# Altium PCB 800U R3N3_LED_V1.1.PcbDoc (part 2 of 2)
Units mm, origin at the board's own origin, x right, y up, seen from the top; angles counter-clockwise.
Board outline 308.48 x 220.22 mm, 4 copper layers (Top Layer, GND, Mid-Layer 2, Bottom Layer); 79 components, 48 nets, 220 pads, 97 vias.
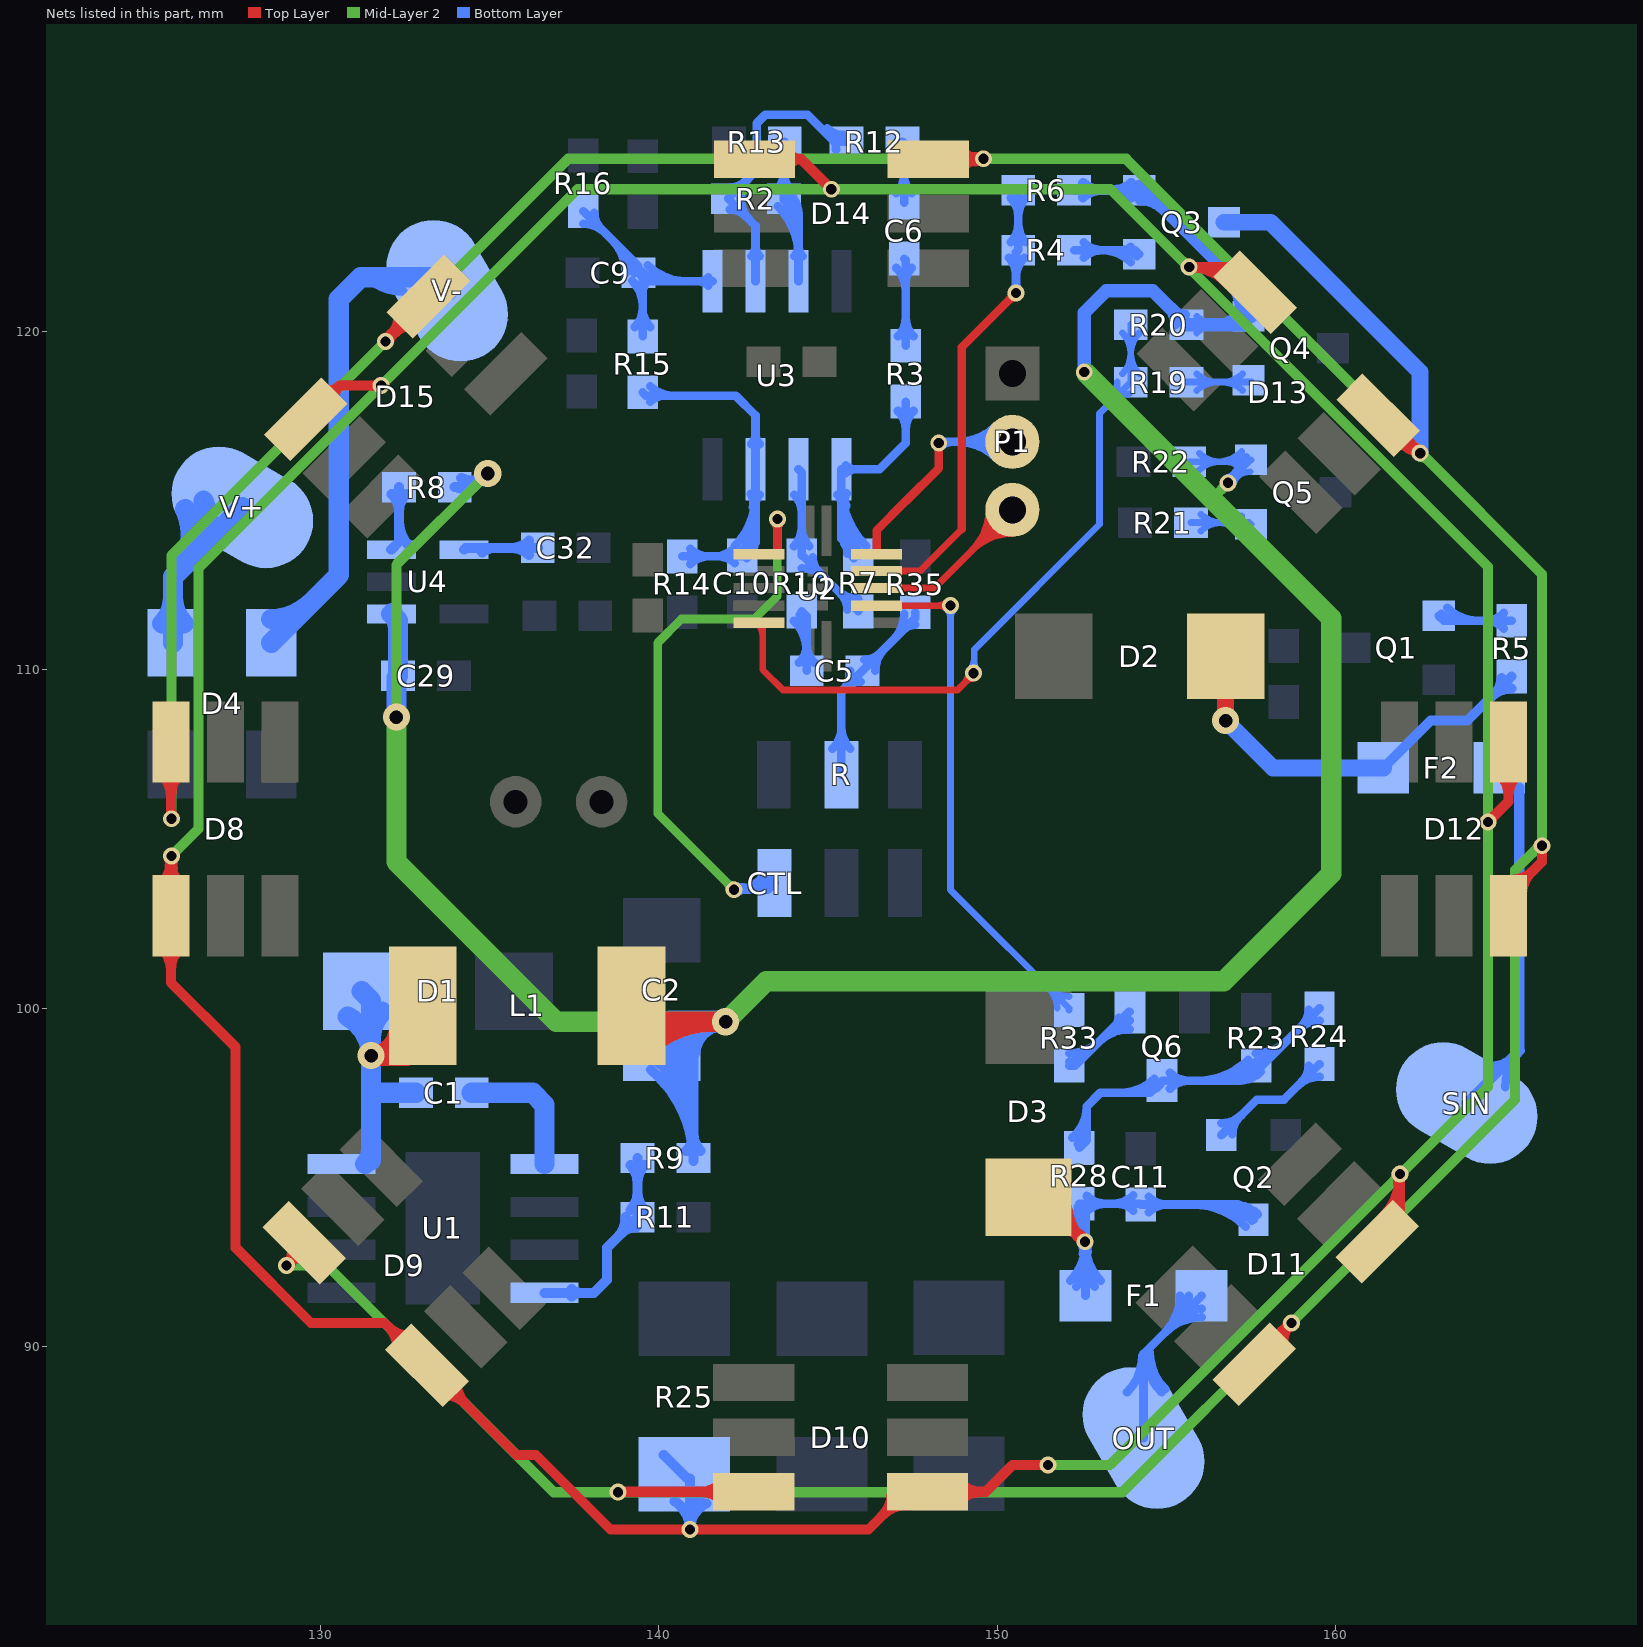
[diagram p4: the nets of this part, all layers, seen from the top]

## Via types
v1: diameter 0.5, hole 0.3, Top Layer to Bottom Layer, 88 vias
v2: diameter 0.8, hole 0.4, Top Layer to Bottom Layer, 6 vias
v3: diameter 0.6, hole 0.3, Top Layer to Bottom Layer, 3 vias

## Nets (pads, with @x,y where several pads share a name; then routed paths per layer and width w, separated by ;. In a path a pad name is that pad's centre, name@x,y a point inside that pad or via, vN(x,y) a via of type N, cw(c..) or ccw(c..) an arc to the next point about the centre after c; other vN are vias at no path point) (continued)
LED_G: R19.2 R20.2 U2.5 | length 26
  Top Layer w0.2: U2.5@142.925,111.356 cw(c142.564,110.995) 143.075,110.995 ; U2.5@142.963,111.393 143.075,111.281 143.075,110 143.675,109.4 148.825,109.4 v1@149.325,109.9 ; 149.026,109.601 ccw(c148.728,109.9) v1@149.15,109.9 ; 149.087,109.662 cw(c149.3,109.448) v1@149.3,109.75
  Bottom Layer w0.2: v1@149.194,110.006 ccw(c148.878,110.322) 149.325,110.322 ; v1@149.325,109.8 149.325,110.6 153.025,114.3 153.025,117.575 R19.2@153.95,118.5 R20.2@153.95,120.2 ; 149.325,110.202 ccw(c149.602,110.202) v1@149.406,110.006 ; 153.267,117.817 ccw(c152.584,118.5) R19.2@153.55,118.5 ; 153.388,117.938 cw(c153.9,117.426) R19.2@153.9,118.15 ; R19.2@153.703,118.747 ccw(c153.105,119.345) 153.95,119.345 ccw(c154.795,119.345) R19.2@154.197,118.747 ; R20.2@153.703,119.953 cw(c153.105,119.355) 153.95,119.355 cw(c154.795,119.355) R20.2@154.197,119.953
  other v1: 149.3,109.9
LED_R: R4.2 R6.2 U2.9 | length 18.4
  Top Layer w0.2: U2.9@146.437,112.918 147.718,112.918 148.95,114.15
  Top Layer w0.254: 148.95,114.15 148.95,119.524 v1(150.557,121.131) ; v1@150.434,121.131 cw(c150.137,121.131) 150.347,120.921 cw(c150.557,120.711) v1@150.557,121.008
  Mid-Layer 2 w0.254: v1(150.557,121.131) v1@150.557,121.182
  Bottom Layer w0.254: R4.2@150.347,122.172 cw(c149.838,121.663) 150.557,121.663 ; R4.2@150.397,122.628 ccw(c149.845,123.18) 150.625,123.18 ccw(c151.405,123.18) R4.2@150.853,122.628 ; R6.2@150.397,123.947 cw(c149.845,123.395) 150.625,123.395 cw(c151.405,123.395) R6.2@150.853,123.947 ; v1@150.47,121.218 ccw(c150.26,121.428) 150.557,121.428 ccw(c150.854,121.428) v1@150.644,121.218 ; v1(150.557,121.131) 150.557,122.332 R4.2@150.625,122.4 R6.2@150.625,124.175 ; 150.557,121.578 cw(c151.397,121.578) R4.2@150.803,122.172
LEDCTL: CTL.1 U2.1 | length 21.7
  Top Layer w0.254: U2.1@142.963,113.418 143.507,113.418 v1(143.507,114.456) ; v1@143.42,114.369 cw(c143.211,114.16) 143.507,114.16 ; 143.507,113.609 ccw(c143.751,113.609) U2.1@143.578,113.436 ; 143.507,114.157 cw(c143.805,114.157) v1@143.594,114.369
  Mid-Layer 2 w0.254: v1@142.102,103.5 ccw(c141.805,103.5) 142.015,103.71 ccw(c142.225,103.92) v1@142.225,103.623 ; v1(142.225,103.5) 139.975,105.75 139.975,110.8 140.675,111.5 142.825,111.5 143.507,112.182 v1(143.507,114.456) ; v1@143.42,114.369 cw(c143.21,114.159) 143.507,114.159 cw(c143.804,114.159) v1@143.594,114.369
  Bottom Layer w0.254: v1@142.286,103.607 ccw(c142.435,103.864) 142.512,103.577 ccw(c142.589,103.29) v1@142.332,103.438 ; v1@142.312,103.413 cw(c142.522,103.203) 142.522,103.5 cw(c142.522,103.797) v1@142.312,103.587 ; 142.757,103.5 ccw(c142.757,104.24) CTL.1@143.332,103.775 ; CTL.1@143.135,103.934 cw(c142.225,104.67) v1(142.225,103.5) 143.225,103.5 CTL.1@143.425,103.7
NetC1_1: C1.1 U1.1 | length 4
  Bottom Layer w0.6: C1.1@134.475,97.5 136.275,97.5 136.625,97.15 U1.1@136.625,95.4
NetC1_2: C1.2 D1.2 L1.1 U1.8 | length 13.4
  Top Layer w0.6: L1.1@132.147,98.6 ccw(c132.147,99.383) L1.1@132.928,99.325 ; L1.1@132.33,99.369 cw(c131.5,99.432) v2(131.5,98.6) L1.1@132.561,98.6 ; L1.1@132.498,99.537 L1.1@133.028,100.067
  Bottom Layer w0.6: D1.2@130.81,99.758 cw(c130.15,98.58) v2@131.5,98.58 ; D1.2@131.225,100.5 131.5,100.225 v2(131.5,98.6) U1.8@131.5,95.5 ; U1.8@131.325,95.4 ccw(c130.903,95.822) 131.5,95.822 ; 131.5,97.5 C1.2@132.825,97.5 ; 131.5,99.112 cw(c132.613,99.112) D1.2@131.826,99.899
NetC5_1: C5.1 R35.1 R.1 | length 10.8
  Bottom Layer w0.254: R.1@145.136,107.664 ccw(c144.5,108.3) 145.4,108.3 ccw(c146.3,108.3) R.1@145.664,107.664 ; R.1@145.4,106.9 145.4,109.35 ; 145.509,109.459 cw(c145.975,108.993) C5.1@145.975,109.652 ; C5.1@145.652,109.971 cw(c144.791,109.959) 145.4,109.35 ; C5.1@146.075,110.298 ccw(c146.075,110.957) 146.541,110.491 ; C5.1@146.398,109.975 cw(c147.298,109.975) 146.662,110.612 ; 146.935,110.885 ccw(c146.17,111.65) R35.1@147.252,111.65 ; 147.237,111.187 cw(c147.575,110.849) R35.1@147.575,111.327 ; R35.1@147.575,111.7 147.575,111.525 C5.1@146.025,109.975 145.4,109.35
NetC5_2: C5.2 R10.1 | length 4.6
  Bottom Layer w0.254: R10.1@143.997,111.447 cw(c143.083,110.533) 144.375,110.533 ; C5.2@144.147,110.203 ccw(c143.595,110.755) 144.375,110.755 ccw(c145.155,110.755) C5.2@144.603,110.203 ; R10.1@144.176,111.626 cw(c143.696,111.146) 144.375,111.146 ; R10.1@144.225,111.725 144.375,111.575 C5.2@144.375,109.975
NetC6_1: C6.1 R3.2 | length 5
  Bottom Layer w0.254: C6.1@147.022,121.872 cw(c146.35,121.2) 147.3,121.2 ; R3.2@147.072,119.853 ccw(c146.52,120.405) 147.3,120.405 ccw(c148.08,120.405) R3.2@147.528,119.853 ; C6.1@147.25,122.15 147.3,122.1 R3.2@147.3,119.575 ; 147.3,121.441 cw(c147.909,121.441) C6.1@147.478,121.872
NetC6_2: C6.2 R12.1 | length 4.3
  Bottom Layer w0.254: C6.2@147.022,124.078 ccw(c146.47,124.63) 147.25,124.63 ccw(c148.03,124.63) C6.2@147.478,124.078 ; R12.1@147.022,125.372 cw(c146.47,124.82) 147.25,124.82 cw(c148.03,124.82) R12.1@147.478,125.372 ; R12.1@147.2,125.6 147.25,125.55 C6.2@147.25,123.8
NetC9_1: C9.1 R15.2 R16.2 U3.5 | length 14.6
  Bottom Layer w0.254: R16.2@137.775,123.177 cw(c137.775,122.276) 138.412,122.913 ; R16.2@137.775,123.55 139.4,121.925 C9.1@139.4,121.725 C9.1@139.525,121.6 ; R16.2@138.098,123.5 ccw(c138.757,123.5) 138.291,123.034 ; 138.622,122.703 cw(c137.644,121.725) C9.1@139.027,121.725 ; 139.055,122.27 cw(c138.511,121.725) C9.1@139.281,121.725 ; C9.1@139.222,121.497 cw(c138.489,120.764) 139.525,120.764 ; R15.2@139.297,120.128 ccw(c138.745,120.68) 139.525,120.68 ccw(c140.305,120.68) R15.2@139.753,120.128 ; C9.1@139.499,121.774 ccw(c140.22,122.495) 140.22,121.475 ; R15.2@139.525,119.85 C9.1@139.525,121.6 ; 139.525,121.126 cw(c140.049,121.126) C9.1@139.678,121.497 ; C9.1@139.678,121.953 ccw(c140.833,123.108) 140.833,121.475 ; U3.5@141.468,121.353 ccw(c141.172,121.057) 141.172,121.475 ccw(c141.172,121.893) U3.5@141.468,121.597 ; U3.5@141.59,121.475 139.65,121.475 C9.1@139.525,121.6
NetC10_1: C10.1 R14.2 R15.1 U3.3 | length 18.8
  Bottom Layer w0.254: R15.1@139.525,118.2 139.625,118.1 142.275,118.1 142.86,117.515 U3.3@142.86,115.925 142.86,113.76 C10.1@142.475,113.375 142.45,113.35 R14.2@140.7,113.35 ; R15.1@139.753,117.922 cw(c140.184,117.491) 140.184,118.1 ; R15.1@139.753,118.378 ccw(c140.425,119.05) 140.425,118.1 ; R14.2@140.928,113.122 cw(c141.48,112.57) 141.48,113.35 cw(c141.48,114.13) R14.2@140.928,113.578 ; 141.635,113.35 ccw(c141.635,114.215) C10.1@142.247,113.603 ; 141.756,113.35 cw(c141.756,112.656) C10.1@142.247,113.147 ; C10.1@142.247,113.653 ccw(c140.766,115.134) U3.3@142.86,115.134 ; C10.1@142.426,113.474 ccw(c141.379,114.521) 142.86,114.521 ; C10.1@142.606,113.294 ccw(c141.992,113.908) 142.86,113.908 ; U3.3@142.714,115.207 cw(c142.261,114.916) 142.787,114.801 ; U3.3@142.738,115.178 cw(c142.442,114.882) 142.86,114.882 cw(c143.278,114.882) U3.3@142.982,115.178 ; U3.3@142.738,116.672 ccw(c142.442,116.968) 142.86,116.968 ccw(c143.278,116.968) U3.3@142.982,116.672 ; 142.824,114.968 cw(c143.113,114.905) U3.3@142.953,115.154
NetC11_1: C11.1 D3.2 F1.2 Q2.3 R28.2 | length 32.7
  Top Layer w0.254: D3.2@150.925,94.42 151.28,94.42 v1(152.6,93.1) ; D3.2@151.186,93.93 cw(c151.402,93.139) D3.2@151.981,93.719 ; D3.2@151.253,93.685 cw(c151.534,92.653) 152.291,93.409 ; D3.2@151.32,93.44 cw(c151.667,92.167) v1(152.6,93.1) ; D3.2@151.814,94.411 ccw(c153.043,94.395) D3.2@152.174,93.526 ; D3.2@152.068,94.407 ccw(c153.885,94.385) v1(152.6,93.1) ; v1@152.477,93.1 ccw(c152.18,93.1) 152.39,93.31 ccw(c152.6,93.52) v1@152.6,93.223 ; v1@152.481,93.068 ccw(c152.194,92.991) 152.343,93.249 ccw(c152.491,93.506) v1@152.568,93.219 ; v1@152.481,93.132 ccw(c152.194,93.209) 152.452,93.357 ccw(c152.709,93.506) v1@152.632,93.219
  Bottom Layer w0.254: F1.2@152.161,91.949 ccw(c151.077,93.033) 152.61,93.033 ccw(c154.144,93.033) F1.2@153.06,91.949 ; R28.2@152.197,93.947 cw(c151.197,92.947) v1@152.61,92.947 ; F1.2@152.341,91.769 ccw(c151.691,92.42) 152.61,92.42 ccw(c153.53,92.42) F1.2@152.88,91.769 ; R28.2@152.376,94.126 cw(c151.811,93.561) 152.61,93.561 ; 152.476,93.448 ccw(c152.86,93.55) v1@152.661,93.207 ; v1@152.493,93.039 cw(c152.155,92.843) 152.533,92.742 ; v1@152.513,93.013 cw(c152.278,92.778) 152.61,92.778 ; v1@152.513,93.187 ccw(c152.278,93.422) 152.61,93.422 ; v1@152.538,92.993 cw(c152.402,92.758) 152.665,92.828 ; F1.2@152.61,91.5 152.61,94.04 R28.2@152.425,94.225 154.225,94.225 C11.1@154.25,94.2 157.125,94.2 Q2.3@157.575,93.75 ; 152.61,92.828 cw(c152.872,92.828) v1@152.687,93.013 ; 152.61,93.372 ccw(c152.872,93.372) v1@152.687,93.187 ; R28.2@152.653,93.997 cw(c153.205,93.445) 153.205,94.225 cw(c153.205,95.005) R28.2@152.653,94.453 ; 152.674,92.795 cw(c152.985,92.878) v1@152.707,93.038 ; 153.41,94.225 ccw(c153.41,95.09) C11.1@154.022,94.478 ; 153.531,94.225 cw(c153.531,93.531) C11.1@154.022,94.022 ; C11.1@154.478,93.972 cw(c155.03,93.42) 155.03,94.2 cw(c155.03,94.98) C11.1@154.478,94.428 ; 155.769,94.2 cw(c155.769,91.969) Q2.3@157.347,93.547 ; 156.382,94.2 cw(c156.382,92.582) Q2.3@157.526,93.726 ; 156.996,94.2 cw(c156.996,93.196) Q2.3@157.706,93.906
NetC32_1: C32.1 U4.4 | length 3.7
  Bottom Layer w0.3: U4.4@134.25,113.55 134.3,113.6 C32.1@136.425,113.6 ; U4.4@134.788,113.462 cw(c135.122,113.128) 135.122,113.6 ; C32.1@136.163,113.388 ccw(c135.651,112.876) 135.651,113.6 ccw(c135.651,114.324) C32.1@136.163,113.812
NetD2_2: D2.2 F2.1 R5.1 | length 13.2
  Top Layer w0.3: D2.2@156.75,110.395 D2.2@156.755,110.4
  Top Layer w0.5: v2(156.75,108.5) D2.2@156.75,110.395
  Bottom Layer w0.3: F2.1@161.411,107.1 162.811,108.5 163.9,108.5 R5.1@165.2,109.8 ; 164.603,109.203 cw(c165.2,108.605) R5.1@165.2,109.45 ; 164.723,109.323 ccw(c164.296,109.75) R5.1@164.9,109.75
  Bottom Layer w0.5: v2(156.75,108.5) 158.15,107.1 F2.1@161.411,107.1
NetD4_2: D4.2 V-.1 | length 17.2
  Bottom Layer w0.254: 131.303,121.653 ccw(c132.458,122.808) V-.1@132.458,121.175
  Bottom Layer w0.6: D4.2@128.55,110.8 130.55,112.8 130.55,120.95 131.2,121.6 133.35,121.6 V-.1@133.75,121.2 ; D4.2@128.55,111.5 ccw(c128.55,113.19) 129.745,111.995
NetD4_3: D4.3 V+.1 | length 10.5
  Bottom Layer w0.6: D4.3@125.332,111.368 ccw(c124.564,112.136) 125.65,112.136 ccw(c126.736,112.136) D4.3@125.968,111.368 ; D4.3@125.65,110.8 125.65,112.75 ; V+.1@126.007,114.741 cw(c124.398,114.002) 125.65,112.75 ; 126.26,113.36 ccw(c125.234,114.386) V+.1@126.553,114.991 ; V+.1@127.7,114.8 125.65,112.75
NetF1_1: F1.1 OUT.1 | length 12.4
  Bottom Layer w0.254: OUT.1@153.836,88.649 ccw(c152.752,89.733) 154.286,89.733 ; OUT.1@154.325,87.3 154.325,89.785 F1.1@156.039,91.5 ; 154.41,89.733 ccw(c155.944,89.733) OUT.1@154.86,88.649 ; 154.51,89.833 ccw(c156.044,89.833) OUT.1@154.96,88.749 ; F1.1@155.404,91.5 cw(c153.871,91.5) 154.955,90.416 cw(c156.039,89.332) F1.1@156.039,90.865 ; F1.1@155.658,91.5 cw(c154.739,91.5) 155.389,90.85 cw(c156.039,90.199) F1.1@156.039,91.119
NetF2_2: F2.2 SIN.1 | length 12.7
  Bottom Layer w0.254: SIN.1@164.6,98.3 ccw(c164.6,99.19) 165.229,98.561 ; SIN.1@165.014,97.667 cw(c166.548,97.667) 165.464,98.751
  Bottom Layer w0.3: SIN.1@163.875,97.2 165.425,98.75 165.425,106.515 F2.2@164.84,107.1
NetP1_2: P1.2 U2.10 | length 10.7
  Top Layer w0.254: U2.10@146.437,113.418 146.437,114.12 147.295,114.977 147.302,114.977 148.275,115.95 v1(148.275,116.7)
  Bottom Layer w0.254: v1(148.275,116.7) 148.31,116.735 P1.2@150.45,116.735 ; v1@148.362,116.613 cw(c148.656,116.319) 148.656,116.735 ; P1.2@149.974,116.259 ccw(c148.825,115.11) 148.825,116.735 ccw(c148.825,118.36) P1.2@149.974,117.211 ; P1.2@150.154,116.439 ccw(c149.438,115.723) 149.438,116.735 ccw(c149.438,117.747) P1.2@150.154,117.031
NetP1_3: P1.3 U2.8 | length 9.5
  Top Layer w0.2: U2.8@146.437,112.418 148.143,112.418 P1.3@150.45,114.725 ; P1.3@149.75,114.725 cw(c148.06,114.725) 149.255,113.53 cw(c150.45,112.335) P1.3@150.45,114.025 ; P1.3@149.95,114.725 cw(c148.743,114.725) 149.596,113.871 cw(c150.45,113.018) P1.3@150.45,114.225
NetQ1_1: Q1.1 R5.2 | length 5
  Bottom Layer w0.254: Q1.1@163.05,111.6 163.2,111.45 R5.2@165.2,111.45 ; Q1.1@163.124,111.649 ccw(c163.604,112.129) 163.604,111.45 ; Q1.1@163.303,111.828 ccw(c164.217,112.742) 164.217,111.45 ; R5.2@164.972,111.222 ccw(c164.42,110.67) 164.42,111.45 ccw(c164.42,112.23) R5.2@164.972,111.678
NetQ2_1: Q2.1 R24.2 | length 6.2
  Bottom Layer w0.254: Q2.1@156.625,96.25 157.675,97.3 158.475,97.3 R24.2@159.525,98.35 ; Q2.1@156.625,96.598 ccw(c156.625,97.438) 157.219,96.844 ; Q2.1@156.948,96.275 cw(c157.667,96.275) 157.159,96.784 ; 158.888,97.713 cw(c159.525,97.077) R24.2@159.525,97.977 ; 159.009,97.834 ccw(c158.543,98.3) R24.2@159.202,98.3
NetQ3_1: Q3.1 R4.1 | length 4.9
  Bottom Layer w0.254: R4.1@152.275,122.4 154.075,122.4 Q3.1@154.2,122.275 ; R4.1@152.553,122.172 cw(c153.105,121.62) 153.105,122.4 cw(c153.105,123.18) R4.1@152.553,122.628 ; 153.093,122.4 cw(c153.093,121.193) Q3.1@153.947,122.047 ; 153.697,122.4 ccw(c153.697,122.753) Q3.1@153.947,122.503 ; 153.707,122.4 cw(c153.707,121.807) Q3.1@154.126,122.226
NetQ4_1: Q4.1 R19.1 | length 4.6
  Bottom Layer w0.2: R19.1@155.6,118.5 Q4.1@157.525,118.5 ; R19.1@155.897,118.253 cw(c156.495,117.655) 156.495,118.5 cw(c156.495,119.345) R19.1@155.897,118.747 ; Q4.1@157.253,118.253 ccw(c156.655,117.655) 156.655,118.5 ccw(c156.655,119.345) Q4.1@157.253,118.747
NetQ5_1: Q5.1 R21.1 | length 4.9
  Bottom Layer w0.2: R21.1@155.725,114.35 157.45,114.35 Q5.1@157.5,114.3 ; R21.1@156.022,114.103 cw(c156.62,113.505) 156.62,114.35 cw(c156.62,115.195) R21.1@156.022,114.597 ; 156.509,114.35 cw(c156.509,113.334) Q5.1@157.228,114.053 ; 156.751,114.35 ccw(c156.751,115.024) Q5.1@157.228,114.547 ; 156.992,114.35 cw(c156.992,113.817) Q5.1@157.369,114.194
NetQ6_1: Q6.1 R33.1 | length 5.8
  Bottom Layer w0.254: R33.1@152.125,98.3 152.3,98.3 153.891,99.891 Q6.1@153.922,99.891 ; R33.1@152.125,98.419 ccw(c152.125,99.129) 152.627,98.627 ; R33.1@152.125,98.673 ccw(c152.125,99.996) 153.06,99.06 ; 153.001,99.001 cw(c153.922,98.079) Q6.1@153.922,99.383 ; 153.434,99.434 cw(c153.922,98.946) Q6.1@153.922,99.637 ; Q6.1@153.507,99.507 ccw(c153.301,99.713) Q6.1@153.592,99.713
NetQ6_3: Q6.3 R23.1 R24.1 R28.1 | length 20.5
  Bottom Layer w0.254: R28.1@152.217,96.172 ccw(c151.439,97.1) 152.65,97.1 ; R28.1@152.381,95.978 ccw(c151.896,96.555) 152.65,96.555 ; R28.1@152.425,95.875 152.65,96.1 152.65,97.1 ; 153.641,97.5 ccw(c153.641,98.914) Q6.3@154.642,97.914 ; 154.255,97.5 ccw(c154.255,98.301) Q6.3@154.821,97.735 ; Q6.3@155.108,97.625 cw(c155.672,97.061) 155.672,97.859 cw(c155.672,98.656) Q6.3@155.108,98.092 ; 155.925,97.859 ccw(c155.925,99.975) R23.1@157.422,98.478 ; 156.539,97.859 ccw(c156.539,99.361) R23.1@157.601,98.299 ; 157.152,97.859 ccw(c157.152,98.748) R23.1@157.781,98.119 ; R23.1@157.65,98.419 ccw(c157.65,99.129) 158.152,98.627 ; R23.1@157.65,98.673 ccw(c157.65,99.996) 158.585,99.06 ; 158.888,99.363 cw(c159.525,98.727) R24.1@159.525,99.627 ; 159.009,99.484 ccw(c158.543,99.95) R24.1@159.202,99.95 ; R24.1@159.525,100 157.825,98.3 R23.1@157.65,98.3 157.209,97.859 Q6.3@154.875,97.859 154.516,97.5 153.05,97.5 152.65,97.1
NetR2_1: R2.1 R12.2 U3.6 | length 12.8
  Bottom Layer w0.254: R2.1@142.1,123.602 cw(c142.1,122.943) 142.566,123.409 ; R2.1@142.1,124.248 ccw(c142.1,124.907) 142.566,124.441 ; 142.687,123.288 cw(c143.323,123.925) 142.423,123.925 cw(c143.323,123.925) 142.687,124.562 ; U3.6@142.738,122.222 ccw(c142.442,122.518) 142.86,122.518 ccw(c143.278,122.518) U3.6@142.982,122.222 ; U3.6@142.86,121.475 142.86,123.115 R2.1@142.05,123.925 142.9,124.775 142.9,126.15 143.15,126.4 144.4,126.4 145.2,125.6 R12.2@145.55,125.6 ; R12.2@145.239,125.363 ccw(c144.338,125.363) 144.975,126 ccw(c145.441,126.466) R12.2@145.441,125.807
NetR2_2: R2.2 R13.1 U3.7 | length 10.9
  Bottom Layer w0.254: R13.1@143.447,125.372 cw(c142.835,124.76) 143.7,124.76 ; R2.2@143.472,124.153 ccw(c142.92,124.705) 143.7,124.705 ccw(c144.48,124.705) R2.2@143.928,124.153 ; R2.2@143.522,123.697 cw(c142.053,122.228) U3.7@144.13,122.228 ; 143.7,124.881 cw(c144.394,124.881) R13.1@143.903,125.372 ; R2.2@143.701,123.876 cw(c142.666,122.841) 144.13,122.841 ; R13.1@143.725,125.6 143.7,125.575 R2.2@143.7,123.925 144.13,123.495 U3.7@144.13,121.475 ; R2.2@143.881,124.056 cw(c143.279,123.454) 144.13,123.454 ; U3.7@144.008,122.222 ccw(c143.712,122.518) 144.13,122.518 ccw(c144.548,122.518) U3.7@144.252,122.222
NetR3_1: R3.1 R7.2 U3.1 | length 14.8
  Bottom Layer w0.254: U3.1@145.278,115.178 cw(c144.982,114.882) 145.4,114.882 cw(c145.818,114.882) U3.1@145.522,115.178 ; U3.1@145.31,115.152 cw(c145.046,114.718) 145.539,114.838 ; 145.4,114.185 ccw(c146.66,114.185) R7.2@145.769,113.294 ; 145.4,114.799 ccw(c147.274,114.799) R7.2@145.949,113.474 ; U3.1@145.4,115.412 ccw(c147.887,115.412) R7.2@146.128,113.653 ; 145.509,114.962 cw(c145.827,115.04) U3.1@145.548,115.21 ; U3.1@145.522,115.803 cw(c145.818,115.507) 145.818,115.925 cw(c145.818,116.343) U3.1@145.522,116.047 ; R7.2@145.577,113.433 ccw(c144.972,113.447) 145.4,113.875 ; R7.2@145.837,113.742 cw(c145.743,114.218) 145.4,113.875 ; R7.2@145.9,113.375 145.4,113.875 ; R3.1@147.072,117.647 cw(c146.52,117.095) 147.3,117.095 cw(c148.08,117.095) R3.1@147.528,117.647 ; R3.1@147.3,117.925 147.3,116.7 146.525,115.925 U3.1@145.4,115.925 145.4,113.875
NetR7_1: R7.1 R10.2 U3.2 | length 9.2
  Bottom Layer w0.254: R10.2@143.997,113.653 ccw(c143.445,114.205) 144.225,114.205 ccw(c145.005,114.205) R10.2@144.453,113.653 ; U3.2@144.008,115.178 cw(c143.483,114.653) 144.225,114.653 ; U3.2@144.13,115.925 144.225,115.83 R10.2@144.225,113.375 144.25,113.375 R7.1@145.9,111.725 ; R10.2@144.225,113.002 cw(c144.225,112.041) 144.904,112.721 ; R10.2@144.548,113.325 ccw(c145.147,113.325) 144.723,112.902 ; 145.263,112.362 ccw(c145.9,112.998) R7.1@145.9,112.098 ; 145.384,112.241 cw(c144.918,111.775) R7.1@145.577,111.775
NetR8_2: R8.2 U4.3 | length 3.9
  Bottom Layer w0.3: U4.3@132.1,113.55 132.325,113.775 R8.2@132.325,115.4 ; R8.2@132.113,115.188 cw(c131.601,114.676) 132.325,114.676 cw(c133.049,114.676) R8.2@132.537,115.188 ; 132.325,114.395 ccw(c133.395,114.395) U4.3@132.638,113.638
NetR9_1: R9.1 R11.2 U1.4 | length 10
  Bottom Layer w0.3: U1.4@136.625,91.59 138.09,91.59 138.475,91.975 138.475,92.925 R11.2@139.375,93.825 R9.1@139.375,95.575 ; U1.4@137.431,91.484 cw(c137.687,91.228) 137.687,91.59 cw(c137.687,91.952) U1.4@137.431,91.696 ; 138.778,93.228 ccw(c138.18,93.825) R11.2@139.025,93.825 ; 138.898,93.348 cw(c139.325,92.921) R11.2@139.325,93.525 ; R11.2@139.163,94.037 ccw(c138.651,94.549) 139.375,94.549 ccw(c140.099,94.549) R11.2@139.587,94.037 ; R9.1@139.163,95.363 cw(c138.651,94.851) 139.375,94.851 cw(c140.099,94.851) R9.1@139.587,95.363
OUTPUT: R33.2 U2.7 | length 18.1
  Top Layer w0.2: U2.7@146.437,111.893 v1@148.625,111.893 ; 148.247,111.893 ccw(c148.247,112.278) v1@148.519,112.006 ; 148.279,111.893 cw(c148.279,111.554) v1@148.519,111.794
  Bottom Layer w0.2: v1@148.519,111.794 cw(c148.263,111.538) 148.625,111.538 cw(c148.987,111.538) v1@148.731,111.794 ; v1(148.625,111.9) 148.625,103.5 152.125,100 R33.2@152.125,99.95 ; R33.2@151.775,100 ccw(c150.93,100) 151.528,100.597 ccw(c152.125,101.195) R33.2@152.125,100.35
R-: D8.1 D9.1 D10.1 D11.1 D12.1 D13.1 D14.1 D15.1 R25.2 | length 165.7
  Top Layer w0.3: D8.1@125.304,101.802 cw(c124.621,101.119) 125.587,101.119 cw(c126.553,101.119) D8.1@125.87,101.802 ; D8.1@125.304,103.667 ccw(c124.621,104.35) 125.587,104.35 ccw(c126.553,104.35) D8.1@125.87,103.667 ; v1@125.513,104.45 cw(c125.227,104.284) 125.546,104.199 ; 125.587,104.227 cw(c125.873,104.227) v1@125.671,104.429 ; v1(125.6,104.5) 125.587,104.487 D8.1@125.587,102.735 125.587,100.763 127.5,98.85 127.5,92.925 129.725,90.7 131.9,90.7 D9.1@133.155,89.445 135.8,86.8 136.375,86.8 138.575,84.6 146.2,84.6 D10.1@147.4,85.8 ; 125.645,104.134 cw(c126.047,104.242) v1@125.687,104.45 ; D15.1@129.57,117.401 130.569,118.4 ; D15.1@130.102,118.255 ccw(c130.197,118.772) 130.569,118.4 ; D15.1@130.424,117.933 cw(c130.941,118.028) 130.569,118.4 ; v1(131.8,118.4) 130.569,118.4 ; D9.1@132.295,89.905 ccw(c131.329,89.905) 132.012,90.588 ccw(c132.695,91.271) D9.1@132.695,90.305 ; D9.1@133.614,88.586 cw(c133.614,87.62) 134.297,88.303 cw(c134.98,88.986) D9.1@134.014,88.986 ; D14.1@142.835,125.088 144.212,125.088 ; D14.1@143.822,124.874 cw(c144.212,124.626) 144.212,125.088 ; D14.1@143.822,125.302 ccw(c144.212,125.549) 144.212,125.088 ; v1(145.1,124.2) 144.212,125.088 ; 146.592,84.992 ccw(c145.872,85.712) D10.1@146.89,85.712 ; 146.645,85.045 cw(c147.29,84.399) D10.1@147.29,85.312 ; D10.1@147.94,85.712 149.662,85.712 150.45,86.5 v1(151.5,86.5) ; D10.1@148.873,85.429 cw(c149.556,84.746) 149.556,85.712 cw(c149.556,86.678) D10.1@148.873,85.995 ; 156.328,121.9 cw(c156.328,120.894) D13.1@157.091,121.549 ; D13.1@156.863,121.354 ccw(c155.675,120.335) v1(155.675,121.9) 156.75,121.9 157.495,121.155 D13.1@157.626,121.155 ; D11.1@161.23,93.105 161.9,93.775 v1(161.9,95.1) ; D11.1@161.406,93.847 ccw(c160.214,95.039) v1@161.9,95.039 ; D11.1@161.618,93.635 ccw(c160.939,94.315) 161.9,94.315 ; v1@161.813,95.05 cw(c161.558,94.902) 161.843,94.826 ; v1(164.5,105.5) 165.113,106.113 D12.1@165.113,107.865 ; D12.1@164.83,106.933 cw(c164.147,106.25) 165.113,106.25 cw(c166.079,106.25) D12.1@165.396,106.933
  Mid-Layer 2 w0.3: v1(125.6,104.5) 126.4,105.3 126.4,113 v1(131.8,118.4) 137.6,124.2 v1(145.1,124.2) 153.35,124.2 164.5,113.05 v1(164.5,105.5) 164.5,97.675 153.325,86.5 v1(151.5,86.5) ; 155.462,122.088 ccw(c155.675,122.302) v1@155.675,122 ; v1@155.775,121.9 ccw(c156.077,121.9) 155.863,121.687 ; 161.712,94.887 ccw(c161.498,95.1) v1@161.8,95.1 ; v1@161.9,95.2 ccw(c161.9,95.502) 162.113,95.288
  Bottom Layer w0.3: R25.2@140.15,86.8 R25.2@140.85,86.1 ; R25.2@140.476,85.432 cw(c139.926,84.598) 140.925,84.598 cw(c141.778,84.598) R25.2@141.41,85.368 ; v1(140.925,84.6) R25.2@140.925,86.1 ; 140.925,85.074 cw(c141.55,85.074) R25.2@141.281,85.639
RED: D8.6 D9.6 D10.6 D11.6 D12.6 D13.6 D14.6 D15.6 Q3.3 | length 160.6
  Top Layer w0.3: D8.6@125.304,106.933 cw(c124.621,106.25) 125.587,106.25 cw(c126.553,106.25) D8.6@125.87,106.933 ; 125.587,105.873 ccw(c125.873,105.873) v1@125.671,105.671 ; D8.6@125.587,107.865 125.587,105.613 v1(125.6,105.6) ; v1@129.095,92.495 cw(c129.527,92.063) D9.6@129.527,92.674 ; v1@129.097,92.374 cw(c129.444,92.281) D9.6@129.264,92.592 ; D9.6@129.143,92.961 cw(c128.6,92.801) v1(129,92.4) 129.527,92.927 D9.6@129.527,93.074 ; v1@131.899,119.797 ccw(c131.807,120.14) 132.115,119.962 ; v1(131.925,119.7) 133.199,120.974 D15.6@133.199,121.03 ; v1@132.016,119.791 ccw(c131.238,120.57) D15.6@132.339,120.57 ; v1@132.022,119.674 cw(c132.528,119.538) 132.266,119.993 ; v1@132.024,119.69 cw(c132.363,119.656) 132.193,119.951 ; 132.152,119.927 cw(c132.739,119.339) D15.6@132.739,120.17 ; v1(138.8,85.7) 138.812,85.712 D10.6@142.81,85.712 ; v1@138.871,85.629 cw(c139.071,85.429) 139.071,85.712 ; D10.6@141.877,85.429 ccw(c141.194,84.746) 141.194,85.712 ccw(c141.194,86.678) D10.6@141.877,85.995 ; D14.6@147.965,125.088 149.588,125.088 v1(149.6,125.1) ; D14.6@148.898,124.805 cw(c149.581,124.122) 149.581,125.088 cw(c149.581,126.054) D14.6@148.898,125.371 ; 149.324,125.157 ccw(c149.401,125.445) v1@149.55,125.187 ; 149.329,125.088 ccw(c149.329,125.371) v1@149.529,125.171 ; 149.353,125.027 ccw(c149.284,125.282) v1@149.513,125.15 ; D11.6@157.601,89.477 157.601,89.601 v1(158.7,90.7) ccw(c159.302,90.098) D11.6@158.458,89.988 ; D11.6@158.061,90.336 ccw(c158.061,91) v1@158.531,90.531 ; 158.392,90.451 ccw(c158.166,90.843) v1@158.603,90.726 ; D13.6@161.255,117.526 v1@162.381,116.4 ; D13.6@161.721,116.667 cw(c161.736,115.755) v1@162.381,116.4 ; D13.6@162.114,117.06 ccw(c163.026,117.045) v1@162.381,116.4 ; 162.126,116.655 ccw(c162.5,117.029) v1@162.5,116.5 ; 162.137,116.541 ccw(c162.359,116.926) v1@162.474,116.497 ; D13.6@162.166,116.773 ccw(c162.679,117.07) v1@162.526,116.497 ; v1(162.5,116.4) v1@162.381,116.4 ; D12.6@165.113,102.735 165.113,103.338 166.1,104.325 v1(166.1,104.8) ; D12.6@165.113,103.785 ccw(c165.113,104.863) 165.875,104.1 ; D12.6@165.513,103.385 cw(c166.366,103.385) 165.763,103.988
  Mid-Layer 2 w0.3: v1(125.6,105.6) 125.6,113.375 v1(131.925,119.7) 137.325,125.1 v1(149.6,125.1) 153.825,125.1 153.825,125.075 v1(162.5,116.4) ; v1(129,92.4) 130.2,92.4 136.9,85.7 v1(138.8,85.7) 153.7,85.7 v1(158.7,90.7) 165.3,97.3 165.3,104.075 166.025,104.8 v1(166.1,104.8) 166.1,112.825 v1@162.512,116.413 ; v1@162.5,116.3 cw(c162.5,115.998) 162.713,116.212 ; 165.801,104.576 cw(c166.1,104.278) v1@166.1,104.7
  Bottom Layer w0.5: Q3.3@156.7,123.225 158.075,123.225 162.5,118.8 v1(162.5,116.4)
VDD_+5V: C2.1 C29.1 L1.2 Q3.2 Q4.2 Q5.2 R6.1 R8.1 R9.2 R20.1 R22.1 U4.1 | length 130.9
  Top Layer w0.2: v1(156.825,115.525) v1@156.825,115.6
  Top Layer w0.6: L1.2@139.196,100.067 139.663,99.6 v2(141.975,99.6) ; L1.2@139.691,98.822 cw(c141.569,96.944) 141.569,99.6 ; L1.2@139.691,99.812 ccw(c140.203,100.324) 140.203,99.6
  Mid-Layer 2 w0.3: v2(132.25,108.6) 132.25,113.1 v2(134.95,115.8) ; 156.363,115.037 156.363,115.063 v1(156.825,115.525)
  Mid-Layer 2 w0.6: v2(132.25,108.6) 132.25,104.325 136.975,99.6 v2(141.975,99.6) 143.175,100.8 156.7,100.8 159.875,103.975 159.875,111.525 156.363,115.037 v1@152.65,118.75
  Bottom Layer w0.2: R22.1@155.675,116.15 Q5.2@157.45,116.15 ; R20.1@155.897,119.953 cw(c156.495,119.355) 156.495,120.2 cw(c156.495,121.045) R20.1@155.897,120.447 ; R22.1@155.972,115.903 cw(c156.57,115.305) 156.57,116.15 cw(c156.57,116.995) R22.1@155.972,116.397 ; 156.172,120.2 ccw(c156.172,121.728) Q4.2@157.253,120.647 ; 156.509,116.15 ccw(c156.509,117.166) Q5.2@157.228,116.447 ; 156.655,120.2 ccw(c156.655,121.245) Q4.2@157.394,120.506 ; 156.751,116.15 cw(c156.751,115.476) Q5.2@157.228,115.953 ; v1@156.786,115.67 ccw(c156.681,116.062) Q5.2@157.032,115.859 ; v1(156.825,115.525) Q5.2@157.45,116.15 ; v1@156.825,115.675 ccw(c156.825,116.037) 157.081,115.781 ccw(c157.337,115.525) v1@156.975,115.525 ; v1@156.86,115.56 ccw(c156.22,116.2) Q5.2@157.125,116.2 ; v1@156.864,115.67 ccw(c156.927,115.905) 157.048,115.694 ; v1@156.92,115.62 cw(c157.475,115.065) Q5.2@157.475,115.85 ; v1@156.97,115.486 cw(c157.435,115.362) Q5.2@157.194,115.778 ; v1@156.97,115.564 cw(c157.278,115.646) 157.002,115.806 ; 156.992,116.15 ccw(c156.992,116.683) Q5.2@157.369,116.306 ; Q4.2@157.325,120.2 Q4.2@157.525,120.4 ; Q5.2@157.5,116.2 Q5.2@157.45,116.15
  Bottom Layer w0.3: R8.1@133.975,115.4 134.55,115.4 ; R8.1@134.025,115.4 ccw(c134.267,115.891) 134.654,115.504 ; R8.1@134.158,115.669 ccw(c134.462,116.288) v2(134.95,115.8) 134.55,115.4 ; R8.1@134.283,115.248 cw(c134.55,115.091) 134.55,115.4 ; R8.1@134.283,115.552 ccw(c134.55,115.709) 134.55,115.4 ; R8.1@134.354,115.331 ccw(c133.997,115.95) v2@134.703,115.839 ; C2.1@139.768,98.187 cw(c137.504,95.491) R9.2@141.025,95.491 ; C2.1@139.961,98.417 cw(c138.045,96.135) 141.025,96.135 ; C2.1@140.154,98.647 cw(c138.585,96.779) 141.025,96.779 ; C2.1@140.347,98.877 cw(c139.126,97.422) 141.025,97.422 ; C2.1@140.54,99.106 cw(c139.666,98.066) C2.1@141.025,98.066 ; R9.2@140.813,95.787 ccw(c140.301,96.299) 141.025,96.299 ccw(c141.749,96.299) R9.2@141.237,95.787 ; R9.2@141.025,95.575 C2.1@141.025,98.921 ; R6.1@152.275,124.175 Q3.2@154.2,124.175 154.319,124.175 157.525,120.969 ; R6.1@152.537,123.963 cw(c153.049,123.451) 153.049,124.175 cw(c153.049,124.899) R6.1@152.537,124.387 ; Q3.2@153.963,123.963 ccw(c153.451,123.451) 153.451,124.175 ccw(c153.451,124.899) Q3.2@153.963,124.387 ; Q3.2@154.225,123.875 cw(c154.225,122.923) 154.898,123.596 ; Q3.2@154.525,124.175 ccw(c155.022,124.175) Q3.2@154.671,123.824 ; 155.003,120.797 cw(c154.405,120.2) R20.1@155.25,120.2 ; 155.123,120.677 ccw(c155.55,121.104) R20.1@155.55,120.5 ; 156.568,121.927 cw(c155.041,120.4) Q4.2@157.2,120.4 ; 157.08,121.414 cw(c156.065,120.4) Q4.2@157.5,120.4 ; Q4.2@157.355,120.647 ccw(c157.135,120.969) 157.525,120.969 ; Q4.2@157.525,120.4 157.525,120.969 ; 157.592,120.902 cw(c157.09,120.4) Q4.2@157.8,120.4 ; Q4.2@157.695,120.647 cw(c157.915,120.969) 157.525,120.969
  Bottom Layer w0.4: v1(152.575,118.8) 152.575,120.55 153.225,121.2 154.6,121.2 R20.1@155.6,120.2 Q4.2@157.325,120.2
  Bottom Layer w0.6: U4.1@132.1,111.65 132.3,111.45 C29.1@132.3,109.825 132.25,109.775 v2(132.25,108.6) ; U4.1@132.118,111.668 cw(c131.678,111.228) 132.3,111.228 ; C2.1@140.319,99.627 v2@141.948,99.627 ; C2.1@140.337,98.796 cw(c141.272,98.685) 141.272,99.627 ; C2.1@140.932,98.725 cw(c141.948,98.604) v2@141.948,99.627 ; v2(141.975,99.6) v2@141.948,99.627
pads on no net: U1.5
copper on no net:
  other v3: 145.35,105.3

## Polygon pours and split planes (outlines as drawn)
GND on GND "G" (solid, remove dead copper, pour order 14): 121.3,128.9 168.775,128.9 168.775,82.775 168.7,82.7 121.075,82.7 121.075,128.825 121.15,128.9
AGND on GND "G" (solid, remove dead copper, pour order 10): 136.15,126 136.15,120.325 136.125,120.3 136.325,120.1 139.175,120.1 139.475,119.8 139.675,119.6 139.675,118.2 139.675,106.65 139.625,106.6 139.725,106.5 149.025,106.5 149.025,127.725 149.1,127.8 137.95,127.8 136.15,126
GND on Top Layer "B" (solid, remove dead copper, pour order 13): 121.3,128.9 168.775,128.9 168.775,82.775 168.7,82.7 121.075,82.7 121.075,128.825 121.15,128.9
AGND on Top Layer "T" (solid, remove dead copper, pour order 9): 136.15,126 136.15,120.325 136.125,120.3 136.325,120.1 139.175,120.1 139.475,119.8 139.675,119.6 139.675,118.2 139.675,106.65 139.625,106.6 139.725,106.5 149.025,106.5 149.025,127.725 149.1,127.8 137.95,127.8 136.15,126
AGND on Mid-Layer 2 "B" (solid, remove dead copper, pour order 8): 136.15,126 136.15,120.325 136.125,120.3 136.325,120.1 139.175,120.1 139.475,119.8 139.675,119.6 139.675,118.2 139.675,106.65 139.625,106.6 139.725,106.5 149.025,106.5 149.025,127.725 149.1,127.8 137.95,127.8 136.15,126
GND on Mid-Layer 2 "M" (solid, remove dead copper, pour order 12): 121.3,128.9 168.775,128.9 168.775,82.775 168.7,82.7 121.075,82.7 121.075,128.825 121.15,128.9
GND on Bottom Layer "B" (solid, remove dead copper, pour order 11): 121.3,128.9 168.775,128.9 168.775,82.775 168.7,82.7 121.075,82.7 121.075,128.825 121.15,128.9

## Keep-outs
Keep-Out Layer:
  circle w0.15: c153.8,105.3 r3
  circle w0.15: c145.4,96.7 r3
  lines w0.2: 122.647,103.829 ccw(c145.399,105.308) 122.85,101.934 ccw(c123.344,102.008) 123.344,101.508 123.932,101.508 ccw(c145.399,105.308) 124.499,99.108 124.129,99.108 ccw(c124.129,98.608) 123.652,98.458 ccw(c145.399,105.308) 143.919,82.556 cw(c145.399,82.308) 146.878,82.556 ccw(c145.399,105.308) 167.145,98.458 ccw(c166.668,98.608) 166.668,99.108 166.298,99.108 ccw(c145.399,105.308) 166.865,101.508 167.453,101.508 ccw(c167.453,102.008) 167.948,101.934 ccw(c145.399,105.308) 168.151,103.829 cw(c168.399,105.308) 168.151,106.787 ccw(c145.399,105.308) 146.878,128.06 cw(c145.399,128.308) 143.919,128.06 ccw(c145.399,105.308) 122.647,106.787 cw(c122.399,105.308) 122.647,103.829

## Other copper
Top Layer:
  pour cut-out: 140.6,123.375 141.625,123.375 141.65,123.4 141.65,122.6 140.7,122.6
  pour cut-out: 142.825,105.9 147.9,105.9 147.9,104.7 142.825,104.7
GND:
  pour cut-out: 142.825,105.9 147.9,105.9 147.9,104.7 142.825,104.7
Mid-Layer 2:
  pour cut-out: 134.525,87.7 134.525,89.025 136.975,89.025 137.025,89.075 137.025,87.725
  pour cut-out: 139.475,127.9 140.8,127.9 140.8,125.45 140.85,125.4 139.5,125.4
  pour cut-out: 152.95,120.9 156.5,120.9 156.5,119.025 156.525,119 153.025,119 152.925,119.1
  pour cut-out: 158.875,105.5 162.425,105.5 162.425,103.625 162.45,103.6 158.95,103.6 158.85,103.7
  pour cut-out: 161.8,93.6 165.35,93.6 165.35,91.725 165.375,91.7 161.875,91.7 161.775,91.8
  pour cut-out: 142.825,105.9 147.9,105.9 147.9,104.7 142.825,104.7
Bottom Layer:
  pour cut-out: 130.9,102.8 132.575,102.8 132.675,102.7 132.675,101.525 132.65,101.5 130.95,101.5 130.85,101.6
  pour cut-out: 144.15,105.1 146.5,105.1 146.5,102.425 146.475,102.4 144.225,102.4
  pour cut-out: 149.125,106.7 150.8,106.7 150.9,106.6 150.9,105.425 150.875,105.4 149.175,105.4 149.075,105.5
  pour cut-out: 131.3,124 132.975,124 133.075,123.9 133.075,122.725 133.05,122.7 131.35,122.7 131.25,122.8
  pour cut-out: 142.825,105.9 147.9,105.9 147.9,104.7 142.825,104.7
  pour cut-out: 135.325,95.3 138.725,95.3 138.725,92.2 135.325,92.2
  pour cut-out: 128.875,93.7 131.925,93.7 131.925,92.2 128.875,92.2

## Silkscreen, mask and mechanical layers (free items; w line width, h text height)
Top Overlay:
  text "20160819" at 136.25,94.7 h1.5
  text "800U" at 137.05,93.3 h1.5
  text "R3N3_SENSOR" at 137.05,91.9 h1.5
  text "_V1.1" at 137.5,90.2 h1.5
Bottom Overlay:
  lines w0.2: 136.475,125.5 136.475,125.65 137.225,126.4 138.825,126.4 ; 138.9,126.4 138.825,126.4 ; 139.4,126 139,126.4 138.95,126.4 138.825,126.4 ; 143.331,114.279 143.331,110.806 148.731,110.806 148.731,114.456 143.507,114.456 ; 148.775,112.4 149.3,112.4 ; 154.05,113.5 154.05,108.2 157.3,108.2 157.3,113.5 156.725,113.5 ; 156.725,113.5 156.725,121.3 153,121.3 153,113.5 156.725,113.5 ; 149.35,109.925 153.525,109.925 153.525,113.1 149.35,113.1 149.35,109.925
Mechanical 1:
  circle w0.2: c145.399,83.808 r0.001
  circle w0.2: c145.399,126.808 r0.001
  circle w0.15: c153.8,105.3 r3
  circle w0.15: c145.4,96.7 r3
  lines w0.005: -0.127,0.508 -0.127,210.508 296.873,210.508 296.873,0.508 -0.127,0.508
  lines w0.2: 122.647,103.829 ccw(c145.399,105.308) 122.85,101.934 ccw(c123.344,102.008) 123.344,101.508 123.932,101.508 ccw(c145.399,105.308) 124.499,99.108 124.129,99.108 ccw(c124.129,98.608) 123.652,98.458 ccw(c145.399,105.308) 143.919,82.556 cw(c145.399,82.308) 146.878,82.556 ccw(c145.399,105.308) 167.145,98.458 ccw(c166.668,98.608) 166.668,99.108 166.298,99.108 ccw(c145.399,105.308) 166.865,101.508 167.453,101.508 ccw(c167.453,102.008) 167.948,101.934 ccw(c145.399,105.308) 168.151,103.829 cw(c168.399,105.308) 168.151,106.787 ccw(c145.399,105.308) 146.878,128.06 cw(c145.399,128.308) 143.919,128.06 ccw(c145.399,105.308) 122.647,106.787 cw(c122.399,105.308) 122.647,103.829 ; 142.825,104.7 147.9,104.7 147.9,105.9 142.825,105.9 142.825,104.7
Mechanical 3:
  circle w0.1: c145.399,105.308 r21.5
  circle w0.15: c212.915,114.19 r2.5
  circle w0.15: c213.025,97.09 r2.5
  circle w0.15: c204.695,105.62 r2.5
  circle w0.15: c221.365,105.58 r2.5
  lines w0.2: 121.125,105.3 172.925,105.3 ; 127.052,123.654 163.68,87.026 ; 127.426,87.345 164.054,123.973 ; 135.875,125.9 135.875,116.25 139.575,116.25 139.575,106.525 149.025,106.525 149.025,127.85 ; 145.4,79.075 145.4,129.15 ; 142.825,104.7 147.9,104.7 147.9,105.9 142.825,105.9 142.825,104.7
